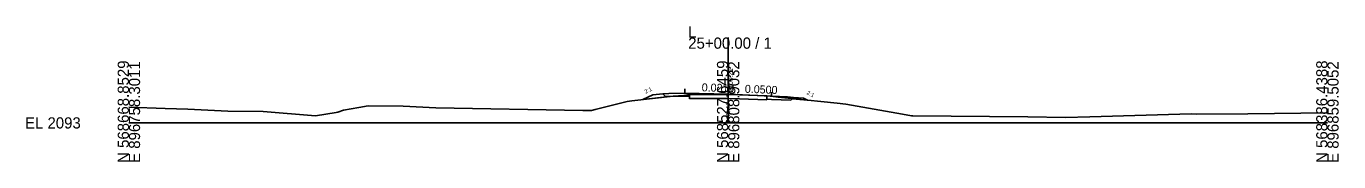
# Model space of a CAD drawing. Extents: x -26 to 1603, y -10 to 13527.
# Drawn here: x -25.7 to 302.8, y 12490.3 to 12524.1 of the extents above; entities that cross this region are included whole.
import ezdxf

# ---------------------------------------------------------------- set-up
doc = ezdxf.new("R2010")
doc.units = 0
for name, color, linetype in [('Default', 7, 'Continuous'), ('Exist XS Center Line Elevation Label', 7, 'Continuous'), ('Exist XS Ground Line', 7, 'Continuous'), ('Old_Level_61', 7, 'Continuous'), ('Old_Level_63', 7, 'Continuous'), ('Prop XS Earthwork Shape', 7, 'Continuous'), ('Prop XS EOT Tick Mark', 7, 'Continuous'), ('Prop XS Finish Grade', 7, 'Continuous'), ('Prop XS Finish Grade Earthwork', 7, 'Continuous'), ('Prop XS Finish Grade Paved Shoulder', 7, 'Continuous'), ('Prop XS Finish Grade Pavement', 7, 'Continuous'), ('Prop XS Side Slope Text', 7, 'Continuous'), ('Prop XS Subgrade Earthwork', 7, 'Continuous'), ('Prop XSC Text', 7, 'Continuous')]:
    doc.layers.add(name, color=color, linetype=linetype)

msp = doc.modelspace()

# ---------------------------------------------------------------- linework, layer by layer
at = {"layer": 'Exist XS Ground Line'}
for p, q in [((57.55, 12503.85), (59.9, 12504.28)), ((59.9, 12504.28), (68.67, 12504.2)), ((68.67, 12504.2), (76.82, 12503.81)), ((118.02, 12503.69), (124.71, 12505.35)), ((124.71, 12505.35), (125.9, 12505.5)), ((125.9, 12505.5), (136.24, 12506.68)), ((136.24, 12506.68), (138.9, 12506.88)), ((138.9, 12506.88), (140.31, 12507.06)), ((140.31, 12507.06), (147.45, 12507.11)), ((147.45, 12507.11), (150.12, 12507.11)), ((150.12, 12507.11), (152.8, 12507)), ((152.8, 12507), (159.71, 12506.76)), ((159.71, 12506.76), (161.24, 12506.6)), ((161.24, 12506.6), (162.52, 12506.42)), ((162.52, 12506.42), (165.87, 12506.07)), ((165.87, 12506.07), (177.32, 12504.91)), ((177.32, 12504.91), (179.42, 12504.72)), ((179.42, 12504.72), (180.84, 12504.44)), ((180.84, 12504.44), (193.67, 12502.15)), ((0, 12503.9), (9.12, 12503.6)), ((9.12, 12503.6), (14.73, 12503.47)), ((14.73, 12503.47), (24.73, 12502.95)), ((24.73, 12502.95), (33.58, 12502.85)), ((33.58, 12502.85), (46.67, 12501.77)), ((46.67, 12501.77), (51.9, 12502.63)), ((51.9, 12502.63), (52.26, 12502.72)), ((52.26, 12502.72), (53.75, 12503.16)), ((53.75, 12503.16), (57.55, 12503.85)), ((76.82, 12503.81), (113.64, 12503.13)), ((113.64, 12503.13), (115.81, 12503.12)), ((115.81, 12503.12), (116.75, 12503.34)), ((116.75, 12503.34), (118.02, 12503.69)), ((193.67, 12502.15), (195.91, 12501.76)), ((195.91, 12501.76), (196.25, 12501.76)), ((196.25, 12501.76), (225.01, 12501.49)), ((225.01, 12501.49), (234.41, 12501.37)), ((234.41, 12501.37), (240.51, 12501.5)), ((240.51, 12501.5), (265.93, 12502.24)), ((265.93, 12502.24), (267.13, 12502.22)), ((267.13, 12502.22), (280.11, 12502.31)), ((280.11, 12502.31), (300, 12502.55))]:
    msp.add_line(p, q, dxfattribs=at)
at = {"layer": 'Old_Level_61'}
for p, q in [((140.29, 12507.05), (140.29, 12506.05)), ((140.29, 12506.05), (140.31, 12506.06)), ((140.31, 12506.06), (141.29, 12506.06)), ((141.29, 12506.06), (147.45, 12506.11)), ((147.45, 12506.11), (150.12, 12506.11)), ((150.12, 12506.11), (152.8, 12506)), ((152.8, 12506), (159.66, 12505.76)), ((159.66, 12505.76), (159.66, 12506.76))]:
    msp.add_line(p, q, dxfattribs=at)
at = {"layer": 'Old_Level_63'}
for p, q in [((150, 12500), (150, 12521.34)), ((0, 12500), (150, 12500)), ((150, 12500), (300, 12500))]:
    msp.add_line(p, q, dxfattribs=at)
at = {"layer": 'Prop XS Earthwork Shape'}
for points in [[(134.34, 12506.56), (133.65, 12507.25), (131.14, 12507.05), (128.68, 12505.81), (135.35, 12506.58)], [(139.14, 12506.66), (135.35, 12506.58), (136.24, 12506.68), (138.9, 12506.88), (140.29, 12507.05), (140.29, 12506.63)], [(161.24, 12506.6), (162.52, 12506.42), (165.87, 12506.07), (166.06, 12506.05), (165.68, 12505.68), (160.86, 12505.88), (159.66, 12505.94), (159.66, 12506.76), (159.71, 12506.76)], [(168.86, 12506.18), (169.9, 12505.66), (166.06, 12506.05), (166.39, 12506.38)]]:
    msp.add_lwpolyline(points, close=True, dxfattribs=at)
at = {"layer": 'Prop XS EOT Tick Mark'}
for p, q in [((139.14, 12507.53), (139.14, 12508.53)), ((160.86, 12506.67), (160.86, 12507.67))]:
    msp.add_line(p, q, dxfattribs=at)
at = {"layer": 'Prop XS Finish Grade'}
for p, q in [((135.14, 12507.37), (133.65, 12507.25)), ((164.86, 12506.5), (166.39, 12506.38))]:
    msp.add_line(p, q, dxfattribs=at)
at = {"layer": 'Prop XS Finish Grade Earthwork'}
for p, q in [((133.65, 12507.25), (131.14, 12507.05)), ((131.14, 12507.05), (128.68, 12505.81)), ((166.39, 12506.38), (168.86, 12506.18)), ((168.86, 12506.18), (169.9, 12505.66))]:
    msp.add_line(p, q, dxfattribs=at)
at = {"layer": 'Prop XS Finish Grade Paved Shoulder'}
for p, q in [((139.14, 12507.45), (135.14, 12507.37)), ((160.86, 12506.67), (164.86, 12506.5))]:
    msp.add_line(p, q, dxfattribs=at)
at = {"layer": 'Prop XS Finish Grade Pavement'}
for q in [(139.14, 12507.45), (160.86, 12506.67)]:
    msp.add_line((150, 12507.21), q, dxfattribs=at)
at = {"layer": 'Prop XS Subgrade Earthwork'}
for p, q in [((134.34, 12506.56), (133.65, 12507.25)), ((139.14, 12506.66), (134.34, 12506.56)), ((140.29, 12506.63), (139.14, 12506.66)), ((140.29, 12506.63), (140.29, 12507.05)), ((159.66, 12505.94), (159.66, 12506.76)), ((159.66, 12505.94), (160.86, 12505.88)), ((160.86, 12505.88), (165.68, 12505.68)), ((165.68, 12505.68), (166.39, 12506.38))]:
    msp.add_line(p, q, dxfattribs=at)

# ---------------------------------------------------------------- texts
at = {"layer": 'Default'}
for s, rotation, p in [('0.0219', 358.3225, (143.36, 12507.9)), ('0.0500', 357.6685, (154.14, 12507.54))]:
    msp.add_text(s, height=2, rotation=rotation, dxfattribs=at).set_placement(p)
at = {"layer": 'Exist XS Center Line Elevation Label'}
msp.add_text('2100.11', height=1, rotation=90, dxfattribs=at).set_placement((150.5, 12500.11))
at = {"layer": 'Old_Level_63'}
for s, p in [('L', (140, 12521.34)), ('25+00.00 / 1', (140, 12518.54)), ('EL 2093', (-26, 12498.6))]:
    msp.add_text(s, height=2.8, dxfattribs=at).set_placement(p)
for s, p in [('N 568668.8529', (0, 12490)), ('E 896758.3011', (2.8, 12490)), ('N 568527.6459', (150, 12490)), ('E 896808.9032', (152.8, 12490)), ('N 568386.4388', (300, 12490)), ('E 896859.5052', (302.8, 12490))]:
    msp.add_text(s, height=2.8, rotation=90, dxfattribs=at).set_placement(p)
at = {"layer": 'Prop XS Side Slope Text'}
for rotation, p in [(26.565, (129.36, 12507.27)), (333.4349, (169.56, 12507.24))]:
    msp.add_text('2:1', height=1, rotation=rotation, dxfattribs=at).set_placement(p)
at = {"layer": 'Prop XSC Text'}
msp.add_text(' 2100.21', height=1.2, rotation=90, dxfattribs=at).set_placement((151.2, 12507.21))

doc.saveas('drawing.dxf')
